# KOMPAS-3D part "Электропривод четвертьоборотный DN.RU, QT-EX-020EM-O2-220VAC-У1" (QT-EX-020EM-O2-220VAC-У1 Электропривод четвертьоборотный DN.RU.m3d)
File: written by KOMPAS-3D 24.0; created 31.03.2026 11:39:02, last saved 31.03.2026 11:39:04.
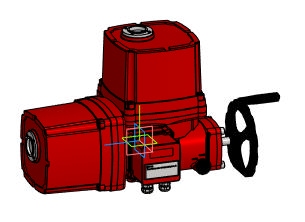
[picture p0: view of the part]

Document properties: Автор: DN.RU; Полное имя файла: D:\PROJECT CAD\DN.RU\...194\Исходники\QT-EX-020EM-O2-220VAC-У1\QT-EX-020EM-O2-220VAC-У1 Электропривод четвертьоборотный DN.RU.m3d

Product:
- Body: Твердое тело1  | qty 1
    Масса: 75.932895
- Part/product: Электропривод четвертьоборотный DN.RU  | designation QT-EX-020EM-O2-220VAC-У1
    Масса: 15
    Раздел спецификации: Прочие изделия
    Комментарий: D300-04903
    Примечание: D300-04903
    additional columns: Сталь

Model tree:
1. Твердое тело1  (labels: Твердое тело1)

Expressions: QT-EX-020EM-O2-220VAC-У1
